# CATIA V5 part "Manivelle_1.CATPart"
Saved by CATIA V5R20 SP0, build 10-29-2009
Part number: Manivelle_1
Publications: "Corps_manivelle", "Axe_pivot_point_A", "Plan_ref", "Axe_pivot_manivelle_1_point_B"
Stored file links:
  C:\Users\J\IAO_2012_jgossard\Manivelle_1.CATPart
  C:\Users\J\IAO_2012_jgossard\squelette_mecanisme_presse.CATProduct

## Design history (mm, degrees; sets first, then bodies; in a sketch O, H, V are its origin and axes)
Set1
  Point1 "Point_A": linked copy from another document
  Point2 "Point_B": linked copy from another document
  Plane1 "Plan_ref": linked copy from another document
Body1 (main body)
  Line1 "Corps_manivelle": type PtPt, FirstPoint Point1, SecondPoint Point2
  Line2 "Axe_pivot_point_A": type Normal, RefPoint Point1, RefSkin Plane1, Start 0, End 10
  Line3 "Axe_pivot_manivelle_1_point_B": type Normal, RefPoint Point2, RefSkin Plane1, Start 0, End 10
